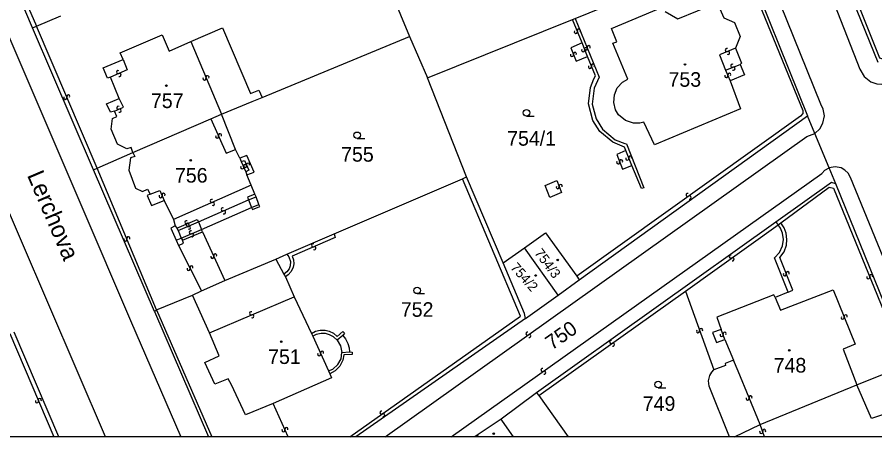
# Model space of a CAD drawing. Extents: x -600391 to -599491, y -1160176 to -1159402.
# Drawn here: x -599892 to -599792.2, y -1160176.1 to -1160127.2 of the extents above; entities that cross this region are included whole.
import ezdxf

# ---------------------------------------------------------------- set-up
doc = ezdxf.new("R2010")
doc.units = 0
for name, color, linetype in [('Level 1', 7, 'Continuous'), ('Level 11', 7, 'Continuous'), ('Level 13', 7, 'Continuous'), ('Level 3', 7, 'Continuous'), ('Level 4', 7, 'Continuous'), ('Level 5', 7, 'Continuous'), ('Vrstva 63', 7, 'Continuous')]:
    doc.layers.add(name, color=color, linetype=linetype)

msp = doc.modelspace()

# ---------------------------------------------------------------- linework, layer by layer
at = {"layer": 'Level 1'}
for p, q in [((-599876.01, -1160161.48), (-599869.717, -1160176.079)), ((-599832.84, -1160162.3), (-599852.573, -1160176.079)), ((-599887.127, -1160176.079), (-599892.35, -1160163.9)), ((-599831.32, -1160171.27), (-599827.876, -1160176.079)), ((-599808.541, -1160176.079), (-599805.56, -1160174.64)), ((-599838.48, -1160175.88), (-599838.76, -1160176.079)), ((-599838.48, -1160175.88), (-599838.343, -1160176.079))]:
    msp.add_line(p, q, dxfattribs=at)
for points in [[(-599791.84, -1160132.5), (-599801.62, -1160108.39)], [(-599890.2, -1160128.43), (-599897.21, -1160111.98)], [(-599853.03, -1160113.33), (-599846.33, -1160129.46)], [(-599827.06, -1160127.37), (-599808.13, -1160119.63)], [(-599807.77, -1160119.48), (-599800.05, -1160138.71)], [(-599809.06, -1160134.61), (-599807.83, -1160137.86), (-599817.85, -1160142.06), (-599819.07, -1160139.44), (-599819.57, -1160139.55), (-599820.28, -1160139.56), (-599821.23, -1160139.24), (-599822.03, -1160138.56), (-599822.37, -1160137.99), (-599822.59, -1160137.16), (-599822.52, -1160136.26), (-599822.18, -1160135.44), (-599821.57, -1160134.77), (-599820.95, -1160134.42), (-599822.69, -1160130.25), (-599822.23, -1160130.06), (-599822.86, -1160128.51), (-599816.84, -1160126)], [(-599816.6, -1160126.56), (-599815.13, -1160127.38), (-599810.56, -1160125.53), (-599809.78, -1160127.28), (-599808.53, -1160127.84), (-599807.89, -1160129.47), (-599808.43, -1160130.81)], [(-599889.74, -1160128.26), (-599886.89, -1160127.03)], [(-599844.24, -1160134.28), (-599827.37, -1160127.48)], [(-599827.37, -1160127.48), (-599827.06, -1160127.37)], [(-599890.2, -1160128.43), (-599889.74, -1160128.26)], [(-599883.1, -1160144.98), (-599890.2, -1160128.43)], [(-599871.8, -1160130.05), (-599868.1, -1160128.45), (-599864.85, -1160136.08), (-599863.88, -1160135.71), (-599863.48, -1160136.56)], [(-599879.67, -1160132.15), (-599879.99, -1160131.36), (-599875.13, -1160129.28), (-599874.32, -1160131.17), (-599871.8, -1160130.05)], [(-599863.48, -1160136.56), (-599846.33, -1160129.46)], [(-599846.33, -1160129.46), (-599844.24, -1160134.28)], [(-599808.43, -1160130.81), (-599807.72, -1160132.57), (-599807.88, -1160132.7)], [(-599881.13, -1160134.21), (-599881.49, -1160134.31), (-599881.98, -1160133.11), (-599879.67, -1160132.15)], [(-599807.88, -1160132.7), (-599807.37, -1160133.92), (-599809.06, -1160134.61)], [(-599880.11, -1160136.67), (-599881.13, -1160134.21)], [(-599839.71, -1160145.79), (-599844.24, -1160134.28)], [(-599880.68, -1160138.16), (-599881.13, -1160138.28), (-599881.6, -1160137.29), (-599880.11, -1160136.67)], [(-599868.23, -1160138.5), (-599864.65, -1160137.02), (-599863.48, -1160136.56)], [(-599878.52, -1160142.95), (-599878.72, -1160142.39), (-599879.22, -1160142.53), (-599880.31, -1160142), (-599881.07, -1160140.26), (-599880.91, -1160139), (-599880.38, -1160138.76), (-599880.68, -1160138.16)], [(-599869.44, -1160139.03), (-599868.23, -1160138.5)], [(-599866.57, -1160142.6), (-599868.23, -1160138.5)], [(-599826.6, -1160157.81), (-599800.05, -1160138.71)], [(-599799.2, -1160140.74), (-599800.05, -1160138.71)], [(-599878.52, -1160142.95), (-599869.44, -1160139.03)], [(-599797.53, -1160144.75), (-599799.2, -1160140.74)], [(-599882.68, -1160144.77), (-599878.52, -1160142.95)], [(-599878.52, -1160142.95), (-599878.29, -1160143.42), (-599878.79, -1160143.6), (-599878.98, -1160145.04), (-599878.22, -1160147.11), (-599877.4, -1160147.51), (-599876.81, -1160147.23), (-599876.53, -1160147.81)], [(-599866.1, -1160143.63), (-599866.57, -1160142.6)], [(-599865.26, -1160145.56), (-599864.43, -1160145.24), (-599865.27, -1160143.32), (-599866.1, -1160143.63)], [(-599883.1, -1160144.98), (-599882.68, -1160144.77)], [(-599796.75, -1160146.62), (-599797.53, -1160144.75)], [(-599876.01, -1160161.48), (-599883.1, -1160144.98)], [(-599864.78, -1160146.78), (-599865.26, -1160145.56)], [(-599840.19, -1160146.03), (-599839.71, -1160145.79)], [(-599835.46, -1160155.82), (-599839.71, -1160145.79)], [(-599864.34, -1160147.83), (-599864.78, -1160146.78)], [(-599855.13, -1160152.45), (-599840.19, -1160146.03)], [(-599796.75, -1160146.62), (-599797.27, -1160146.47), (-599803.72, -1160151.07)], [(-599788.26, -1160167.58), (-599796.75, -1160146.62)], [(-599876.53, -1160147.81), (-599876.85, -1160147.99), (-599876.37, -1160149.15), (-599874.88, -1160148.56)], [(-599864.2, -1160148.11), (-599864.34, -1160147.83)], [(-599874.88, -1160148.56), (-599873.8, -1160150.78)], [(-599863.87, -1160149.01), (-599864.2, -1160148.11)], [(-599870.53, -1160151.93), (-599864.73, -1160149.37)], [(-599864.73, -1160149.37), (-599864.63, -1160149.6), (-599863.77, -1160149.25), (-599863.87, -1160149.01)], [(-599873.8, -1160150.78), (-599873.6, -1160151.52)], [(-599873.6, -1160151.52), (-599874.13, -1160151.78), (-599873.48, -1160153.16)], [(-599870.41, -1160152.21), (-599870.53, -1160151.93)], [(-599803.72, -1160151.07), (-599831.58, -1160170.96)], [(-599802.29, -1160159.24), (-599803.9, -1160155.23), (-599803.32, -1160154.61), (-599802.94, -1160153.84), (-599802.85, -1160153.1), (-599802.96, -1160152.34), (-599803.21, -1160151.77), (-599803.48, -1160151.37)], [(-599803.72, -1160151.07), (-599803.48, -1160151.37)], [(-599872.75, -1160153.18), (-599870.41, -1160152.21)], [(-599860.62, -1160154.82), (-599855.13, -1160152.45)], [(-599832.98, -1160154.05), (-599830.53, -1160152.3), (-599826.9, -1160157.38)], [(-599873.48, -1160153.16), (-599873.21, -1160153.8)], [(-599873.21, -1160153.8), (-599872.62, -1160153.54), (-599872.75, -1160153.18)], [(-599861.89, -1160155.38), (-599860.62, -1160154.82)], [(-599835.46, -1160155.82), (-599832.98, -1160154.05)], [(-599829.04, -1160159.57), (-599832.98, -1160154.05)], [(-599867.81, -1160157.86), (-599861.89, -1160155.38)], [(-599861.89, -1160155.38), (-599860.98, -1160157.12)], [(-599832.84, -1160162.3), (-599832.96, -1160161.72), (-599835.46, -1160155.82)], [(-599870.55, -1160159.06), (-599867.81, -1160157.86)], [(-599860.98, -1160157.12), (-599860.79, -1160157.44)], [(-599860.79, -1160157.44), (-599859.77, -1160159.76)], [(-599829.04, -1160159.57), (-599826.6, -1160157.81)], [(-599826.9, -1160157.38), (-599826.6, -1160157.81)], [(-599875.76, -1160161.28), (-599871.6, -1160159.58)], [(-599871.6, -1160159.58), (-599870.55, -1160159.06)], [(-599869.63, -1160163.97), (-599871.6, -1160159.58)], [(-599859.77, -1160159.76), (-599857.76, -1160164.03)], [(-599832.84, -1160162.3), (-599829.04, -1160159.57)], [(-599803.83, -1160159.84), (-599803.98, -1160159.53), (-599810.61, -1160162.15), (-599810.09, -1160163.56)], [(-599802.29, -1160159.24), (-599803.83, -1160159.84)], [(-599876.01, -1160161.48), (-599875.76, -1160161.28)], [(-599857.76, -1160164.03), (-599857.3, -1160163.78), (-599856.72, -1160163.64), (-599856.15, -1160163.65), (-599855.68, -1160163.77), (-599855.19, -1160164.02), (-599854.76, -1160164.41), (-599854.12, -1160163.82), (-599853.89, -1160164), (-599854.11, -1160164.29)], [(-599810.09, -1160163.56), (-599811.09, -1160163.93), (-599810.63, -1160165.08), (-599809.65, -1160164.73)], [(-599862.2, -1160172.2), (-599865.41, -1160173.53), (-599867.04, -1160170.03), (-599867.43, -1160169.32), (-599868.98, -1160169.94), (-599870.15, -1160167.4), (-599868.5, -1160166.64), (-599869.63, -1160163.97)], [(-599854.11, -1160164.29), (-599853.81, -1160164.67), (-599853.53, -1160165.19), (-599853.37, -1160165.71), (-599853.31, -1160166.18)], [(-599809.65, -1160164.73), (-599808.67, -1160167.14)], [(-599853.31, -1160166.18), (-599853.02, -1160166.21), (-599853.03, -1160166.5), (-599853.99, -1160166.52), (-599854.1, -1160167.15), (-599854.45, -1160167.85), (-599854.99, -1160168.39), (-599855.62, -1160168.72)], [(-599808.67, -1160167.14), (-599809.64, -1160167.54), (-599809.57, -1160167.78), (-599810.93, -1160168.29)], [(-599794.31, -1160170.02), (-599788.61, -1160167.71)], [(-599855.62, -1160168.72), (-599855.43, -1160169.21), (-599862.2, -1160172.2)], [(-599809.113, -1160176.079), (-599811.49, -1160170.18), (-599811.57, -1160169.55), (-599811.42, -1160168.95), (-599811.19, -1160168.56), (-599810.93, -1160168.29)], [(-599805.56, -1160174.64), (-599794.31, -1160170.02)], [(-599790.274, -1160176.079), (-599791.31, -1160173.52), (-599792.62, -1160173.94), (-599794.31, -1160170.02)], [(-599831.58, -1160170.96), (-599835.7, -1160174)], [(-599831.58, -1160170.96), (-599831.32, -1160171.27)], [(-599835.7, -1160174), (-599838.48, -1160175.88)], [(-599834.234, -1160176.079), (-599835.52, -1160174.26), (-599835.7, -1160174)]]:
    msp.add_lwpolyline(points, dxfattribs=at)
at = {"layer": 'Level 13'}
for centre, start, end in [((-599826.992, -1160128.907), 149.28342, 21.38141), ((-599826.649, -1160128.772), 329.06896, 201.65896), ((-599826.142, -1160131.046), 148.79803, 20.89603), ((-599825.841, -1160130.839), 149.3647, 21.9547), ((-599825.798, -1160130.914), 328.58357, 201.17357), ((-599825.499, -1160130.702), 329.57916, 201.67715), ((-599809.43, -1160131.03), 59.90926, 292.49926), ((-599827.451, -1160131.608), 148.95969, 21.54969), ((-599827.108, -1160131.473), 329.17414, 201.27214), ((-599809.29, -1160131.371), 240.12371, 112.22171), ((-599825.351, -1160132.98), 150.20639, 22.30439), ((-599825.01, -1160132.839), 329.99193, 202.58193), ((-599808.796, -1160132.858), 58.705, 290.80299), ((-599880.235, -1160133.602), 61.44708, 294.03708), ((-599880.086, -1160133.939), 241.66154, 113.75953), ((-599809.491, -1160134.059), 149.35374, 21.94374), ((-599809.149, -1160133.922), 329.56819, 201.66619), ((-599808.664, -1160133.202), 238.49054, 111.08054), ((-599870.19, -1160134.341), 150.06162, 22.65162), ((-599869.849, -1160134.2), 330.27607, 202.37407), ((-599886.38, -1160136.591), 150.52524, 22.62323), ((-599886.04, -1160136.448), 330.31078, 202.90078), ((-599880.225, -1160137.751), 61.73519, 293.83318), ((-599880.075, -1160138.088), 241.52073, 114.11073), ((-599868.391, -1160140.957), 331.24212, 203.34012), ((-599868.729, -1160141.104), 151.02767, 23.61767), ((-599821.727, -1160143.985), 328.5907, 200.6887), ((-599821.011, -1160143.678), 149.57045, 21.66845), ((-599820.669, -1160143.541), 329.35599, 201.94599), ((-599865.808, -1160144.686), 151.74839, 24.33839), ((-599865.472, -1160144.535), 331.96285, 204.06085), ((-599865.457, -1160144.528), 152.50445, 25.09445), ((-599865.123, -1160144.373), 332.71891, 204.81691), ((-599822.072, -1160144.116), 148.37625, 20.96625), ((-599829.101, -1160146.998), 149.24545, 21.83545), ((-599828.758, -1160146.862), 329.45991, 201.5579), ((-599875.3, -1160148.041), 149.94887, 22.53887), ((-599874.959, -1160147.9), 330.16333, 202.26132), ((-599813.986, -1160147.91), 72.73964, 305.32964), ((-599869.364, -1160148.611), 61.0736, 293.6636), ((-599869.217, -1160148.949), 241.28806, 113.38605), ((-599813.774, -1160148.211), 252.9541, 125.05209), ((-599868.063, -1160149.59), 61.11563, 293.21363), ((-599867.917, -1160149.929), 240.90117, 113.49117), ((-599872.301, -1160151.09), 60.39823, 292.49622), ((-599872.151, -1160151.37), 60.45451, 292.55251), ((-599872.159, -1160151.43), 240.18377, 112.77377), ((-599872.009, -1160151.71), 240.24006, 112.83006), ((-599879.05, -1160152.95), 329.89878, 202.48878), ((-599871.78, -1160152.26), 60.33651, 292.4345), ((-599871.639, -1160152.6), 240.12205, 112.71205), ((-599879.391, -1160153.09), 150.11324, 22.21123), ((-599857.553, -1160153.771), 60.61912, 293.20912), ((-599857.408, -1160154.11), 240.83358, 112.93158), ((-599868.942, -1160154.964), 332.08353, 204.18153), ((-599808.976, -1160155.089), 73.01585, 305.11385), ((-599869.278, -1160155.116), 151.86908, 24.45908), ((-599808.763, -1160155.39), 252.8014, 125.3914), ((-599872.045, -1160156.512), 153.98416, 26.57416), ((-599871.715, -1160156.348), 334.19861, 206.29661), ((-599802.348, -1160157.023), 328.59673, 201.18673), ((-599802.692, -1160157.156), 148.81119, 20.90919), ((-599792.981, -1160157.489), 149.38562, 21.97562), ((-599792.639, -1160157.352), 329.60007, 201.69807), ((-599864.771, -1160161.69), 60.49413, 292.59213), ((-599864.628, -1160162.03), 240.27968, 112.86968), ((-599795.608, -1160162.053), 329.25189, 201.34988), ((-599795.951, -1160162.188), 149.03743, 21.62743), ((-599832.626, -1160164.049), 72.85433, 304.95233), ((-599812.773, -1160163.762), 147.07628, 19.66628), ((-599812.426, -1160163.639), 327.29074, 199.38873), ((-599809.697, -1160164.076), 327.76797, 200.35797), ((-599832.414, -1160164.35), 252.63988, 125.22988), ((-599822.896, -1160165.029), 72.87545, 304.97345), ((-599810.043, -1160164.203), 147.98243, 20.08042), ((-599822.684, -1160165.33), 252.66099, 125.25099), ((-599856.858, -1160166.446), 151.65537, 24.24537), ((-599856.521, -1160166.295), 331.86983, 203.96783), ((-599830.885, -1160168.299), 72.79057, 304.88857), ((-599830.674, -1160168.6), 252.57612, 125.16612), ((-599889.69, -1160171.931), 150.13945, 22.72945), ((-599889.35, -1160171.79), 330.35391, 202.45191), ((-599807.011, -1160171.609), 149.88753, 21.98553), ((-599806.67, -1160171.47), 329.67307, 202.26307), ((-599849.615, -1160173.248), 72.6078, 304.70579), ((-599849.404, -1160173.551), 252.39334, 124.98334), ((-599861.009, -1160175.324), 151.4049, 23.5029), ((-599860.672, -1160175.176), 331.19045, 203.78045), ((-599805.434, -1160175.502), 147.49858, 19.59658), ((-599805.087, -1160175.377), 327.28413, 199.87413)]:
    msp.add_arc(centre, 0.184, start, end, dxfattribs=at)
at = {"layer": 'Level 3'}
for p, q in [((-599875.76, -1160161.28), (-599869.359, -1160176.079)), ((-599892.83, -1160164.06), (-599887.733, -1160176.079)), ((-599860.471, -1160176.079), (-599862.2, -1160172.2)), ((-599805.033, -1160176.079), (-599805.56, -1160174.64))]:
    msp.add_line(p, q, dxfattribs=at)
for points in [[(-599846.4, -1159952.01), (-599848.08, -1159953.82), (-599859.23, -1159965.79), (-599859.58, -1159966.58), (-599859.93, -1159967.38), (-599860.05, -1159968.25), (-599859.84, -1159969.13), (-599859.47, -1159970.12), (-599859.1, -1159971.11), (-599852.79, -1159986.79), (-599837.18, -1160025.28), (-599821.6, -1160063.84), (-599805.47, -1160103.79), (-599793.95, -1160133.25), (-599793.45, -1160134.12), (-599792.68, -1160134.75), (-599791.97, -1160134.96), (-599791.42, -1160135), (-599790.84, -1160134.89)], [(-599799.2, -1160140.74), (-599798.6, -1160140.2), (-599798.25, -1160139.54), (-599798.08, -1160138.71), (-599798.22, -1160137.91), (-599798.5, -1160137.33), (-599811.08, -1160106.17), (-599827.45, -1160065.85), (-599833.86, -1160049.97), (-599836.15, -1160044.36), (-599836.32, -1160043.74), (-599836.62, -1160043.26), (-599837.17, -1160042.81), (-599837.94, -1160042.56), (-599838.86, -1160042.68)], [(-599914.89, -1160070.76), (-599915.43, -1160070.79), (-599916.05, -1160071.01), (-599916.5, -1160071.34), (-599916.83, -1160071.76), (-599917.11, -1160072.47), (-599917.09, -1160073.24), (-599901.01, -1160110.66), (-599884.47, -1160149.28), (-599878.82, -1160162.53), (-599872.946, -1160176.079)], [(-599881.718, -1160176.079), (-599891.61, -1160153.01), (-599908.15, -1160114.37), (-599923.89, -1160077.89), (-599925.96, -1160075.27), (-599927.96, -1160074.98), (-599930.21, -1160075.52)], [(-599799.24, -1160112.99), (-599791.68, -1160131.95), (-599791.12, -1160132.12), (-599781.57, -1160125.33)], [(-599808.13, -1160119.63), (-599800.61, -1160138.07), (-599800.61, -1160138.44), (-599800.86, -1160138.75), (-599826.9, -1160157.38)], [(-599891.2, -1160124.83), (-599889.74, -1160128.26)], [(-599826.28, -1160130.19), (-599827.37, -1160127.48)], [(-599827.06, -1160127.37), (-599824.28, -1160134.18), (-599824.88, -1160135.46), (-599825.08, -1160137.34), (-599824.65, -1160139.04), (-599823.91, -1160140.25), (-599822.41, -1160141.5), (-599821.31, -1160141.92), (-599821.11, -1160141.97), (-599819.07, -1160147.06), (-599819.36, -1160147.15), (-599820.48, -1160144.48)], [(-599882.68, -1160144.77), (-599889.74, -1160128.26)], [(-599871.8, -1160130.05), (-599868.23, -1160138.5)], [(-599826.28, -1160130.19), (-599827.59, -1160130.76), (-599826.97, -1160132.31), (-599825.66, -1160131.77)], [(-599825.66, -1160131.77), (-599826.28, -1160130.19)], [(-599808.43, -1160130.81), (-599810.29, -1160131.59), (-599809.57, -1160133.36)], [(-599821.19, -1160142.74), (-599821.33, -1160142.33), (-599822.7, -1160141.77), (-599824.21, -1160140.53), (-599825.02, -1160139.24), (-599825.52, -1160137.3), (-599825.3, -1160135.39), (-599824.89, -1160134.39), (-599824.7, -1160134.05), (-599825.66, -1160131.77)], [(-599879.67, -1160132.15), (-599879.18, -1160133.33), (-599881.13, -1160134.21)], [(-599809.57, -1160133.36), (-599807.88, -1160132.7)], [(-599809.57, -1160133.36), (-599809.06, -1160134.61)], [(-599880.68, -1160138.16), (-599879.62, -1160137.68), (-599880.11, -1160136.67)], [(-599869.44, -1160139.03), (-599867.67, -1160143.03), (-599866.57, -1160142.6)], [(-599849.192, -1160176.079), (-599800.12, -1160141.1), (-599799.2, -1160140.74)], [(-599821.19, -1160142.74), (-599822.23, -1160143.2), (-599821.57, -1160144.9), (-599820.48, -1160144.48)], [(-599820.48, -1160144.48), (-599821.19, -1160142.74)], [(-599866.1, -1160143.63), (-599865.91, -1160144.02)], [(-599865.91, -1160144.02), (-599865.56, -1160143.88), (-599865.02, -1160145.02), (-599865.37, -1160145.2)], [(-599875.76, -1160161.28), (-599882.68, -1160144.77)], [(-599865.91, -1160144.02), (-599865.37, -1160145.2)], [(-599841.512, -1160176.079), (-599798.4, -1160145.42), (-599798.02, -1160145.04), (-599797.53, -1160144.75)], [(-599782.666, -1160176.079), (-599795.05, -1160145.87), (-599795.33, -1160145.36), (-599795.69, -1160145.01), (-599796.15, -1160144.75), (-599796.83, -1160144.62), (-599797.53, -1160144.75)], [(-599865.37, -1160145.2), (-599865.26, -1160145.56)], [(-599864.78, -1160146.78), (-599873.8, -1160150.78)], [(-599853.295, -1160176.079), (-599833.42, -1160162.04), (-599840.19, -1160146.03)], [(-599830.57, -1160146.82), (-599829.21, -1160146.24), (-599828.65, -1160147.62), (-599830.02, -1160148.19), (-599830.57, -1160146.82)], [(-599876.53, -1160147.81), (-599875.38, -1160147.37), (-599874.88, -1160148.56)], [(-599864.34, -1160147.83), (-599865.2, -1160148.18), (-599865.08, -1160148.48)], [(-599803.14, -1160151.17), (-599797.53, -1160147.02), (-599797.02, -1160147.13), (-599788.61, -1160167.71)], [(-599870.9, -1160151.04), (-599865.08, -1160148.48)], [(-599865.08, -1160148.48), (-599864.2, -1160148.11)], [(-599865.08, -1160148.48), (-599864.73, -1160149.37)], [(-599864.73, -1160149.37), (-599863.87, -1160149.01)], [(-599873.43, -1160151.77), (-599871.03, -1160150.75), (-599870.9, -1160151.04)], [(-599873.6, -1160151.52), (-599873.43, -1160151.77)], [(-599873.43, -1160151.77), (-599873.27, -1160152.05)], [(-599873.27, -1160152.05), (-599870.9, -1160151.04)], [(-599872.89, -1160152.93), (-599870.53, -1160151.93)], [(-599870.9, -1160151.04), (-599870.53, -1160151.93)], [(-599814.26, -1160159.1), (-599803.48, -1160151.37)], [(-599803.48, -1160151.37), (-599803.14, -1160151.17)], [(-599802.29, -1160159.24), (-599801.77, -1160159), (-599803.27, -1160155.18), (-599802.78, -1160154.52), (-599802.49, -1160153.75), (-599802.44, -1160153.09), (-599802.54, -1160152.34), (-599802.76, -1160151.75), (-599803.14, -1160151.17)], [(-599873.48, -1160153.16), (-599872.89, -1160152.93)], [(-599873.27, -1160152.05), (-599872.89, -1160152.93)], [(-599872.89, -1160152.93), (-599872.75, -1160153.18)], [(-599870.41, -1160152.21), (-599867.81, -1160157.86)], [(-599855.13, -1160152.45), (-599854.98, -1160152.85), (-599859.98, -1160155.02), (-599859.84, -1160155.45), (-599859.8, -1160155.94), (-599859.88, -1160156.33), (-599860.1, -1160156.81), (-599860.46, -1160157.22), (-599860.79, -1160157.44)], [(-599873.21, -1160153.8), (-599870.55, -1160159.06)], [(-599860.62, -1160154.82), (-599860.39, -1160155.12), (-599860.2, -1160155.64), (-599860.23, -1160156.15), (-599860.36, -1160156.52), (-599860.61, -1160156.86), (-599860.98, -1160157.12)], [(-599869.63, -1160163.97), (-599859.77, -1160159.76)], [(-599831.32, -1160171.27), (-599814.26, -1160159.1)], [(-599814.26, -1160159.1), (-599810.93, -1160168.29)], [(-599803.83, -1160159.84), (-599803.18, -1160161.32), (-599797.05, -1160158.95), (-599794.5, -1160165.3), (-599795.9, -1160165.86), (-599794.31, -1160170.02)], [(-599809.65, -1160164.73), (-599810.09, -1160163.56)], [(-599857.76, -1160164.03), (-599857.61, -1160164.34)], [(-599854.78, -1160164.81), (-599855.2, -1160164.42), (-599855.65, -1160164.19), (-599856.13, -1160164.05), (-599856.64, -1160164.03), (-599857.19, -1160164.14), (-599857.61, -1160164.34)], [(-599857.61, -1160164.34), (-599855.76, -1160168.4)], [(-599854.11, -1160164.29), (-599854.78, -1160164.81)], [(-599854.78, -1160164.81), (-599854.39, -1160165.49), (-599854.21, -1160166.26)], [(-599855.76, -1160168.4), (-599855.26, -1160168.19), (-599854.67, -1160167.67), (-599854.31, -1160167.01), (-599854.21, -1160166.26)], [(-599854.21, -1160166.26), (-599853.31, -1160166.18)], [(-599805.56, -1160174.64), (-599808.13, -1160168.44), (-599808.67, -1160167.14)], [(-599855.76, -1160168.4), (-599855.62, -1160168.72)]]:
    msp.add_lwpolyline(points, dxfattribs=at)
at = {"layer": 'Level 5'}
for p, q in [((-599832.74, -1160138.72), (-599831.865, -1160138.72)), ((-599852.43, -1160141.33), (-599851.555, -1160141.33)), ((-599845.46, -1160159.4), (-599844.585, -1160159.4)), ((-599817.42, -1160170.35), (-599816.545, -1160170.35))]:
    msp.add_line(p, q, dxfattribs=at)
for centre, radius in [((-599814.31, -1160132.71), 0.09), ((-599814.31, -1160132.71), 0.0521), ((-599874.63, -1160135.19), 0.09), ((-599874.63, -1160135.19), 0.0521), ((-599832.74, -1160138.345), 0.375), ((-599852.43, -1160140.955), 0.375), ((-599871.8, -1160143.87), 0.09), ((-599871.8, -1160143.87), 0.0521), ((-599829.1, -1160155.47), 0.09), ((-599829.1, -1160155.47), 0.0521), ((-599831.68, -1160157.29), 0.09), ((-599831.68, -1160157.29), 0.0521), ((-599845.46, -1160159.025), 0.375), ((-599861.27, -1160164.99), 0.09), ((-599861.27, -1160164.99), 0.0521), ((-599802.17, -1160165.99), 0.09), ((-599802.17, -1160165.99), 0.0521), ((-599817.42, -1160169.975), 0.375), ((-599836.55, -1160175.71), 0.09), ((-599836.55, -1160175.71), 0.0521)]:
    msp.add_circle(centre, radius, dxfattribs=at)
at = {"layer": 'Vrstva 63'}
msp.add_lwpolyline([(-600391.008, -1159401.769), (-599490.773, -1159401.769), (-599490.773, -1160176.079), (-600391.008, -1160176.079)], close=True, dxfattribs=at)

# ---------------------------------------------------------------- texts
at = {"layer": 'Level 11'}
msp.add_text('Lerchova', height=2, rotation=293.15499, dxfattribs=at).set_placement((-599890.868, -1160145.594))
at = {"layer": 'Level 4'}
for s, p in [('753', (-599816.217, -1160135.31)), ('757', (-599876.425, -1160137.79)), ('754/1', (-599834.988, -1160142.17)), ('755', (-599854.301, -1160144.03)), ('756', (-599873.63, -1160146.47)), ('752', (-599847.355, -1160162.1)), ('751', (-599862.793, -1160167.59)), ('748', (-599803.986, -1160168.59)), ('749', (-599819.209, -1160173.05))]:
    msp.add_text(s, height=1.7, dxfattribs=at).set_placement(p)
for s, height, rotation, p in [('754/3', 1.14, 306.8325, (-599831.874, -1160154.68)), ('754/2', 1.14, 311.39082, (-599834.676, -1160156.41)), ('750', 1.7, 35.1, (-599829.775, -1160166.028))]:
    msp.add_text(s, height=height, rotation=rotation, dxfattribs=at).set_placement(p)

doc.saveas('drawing.dxf')
